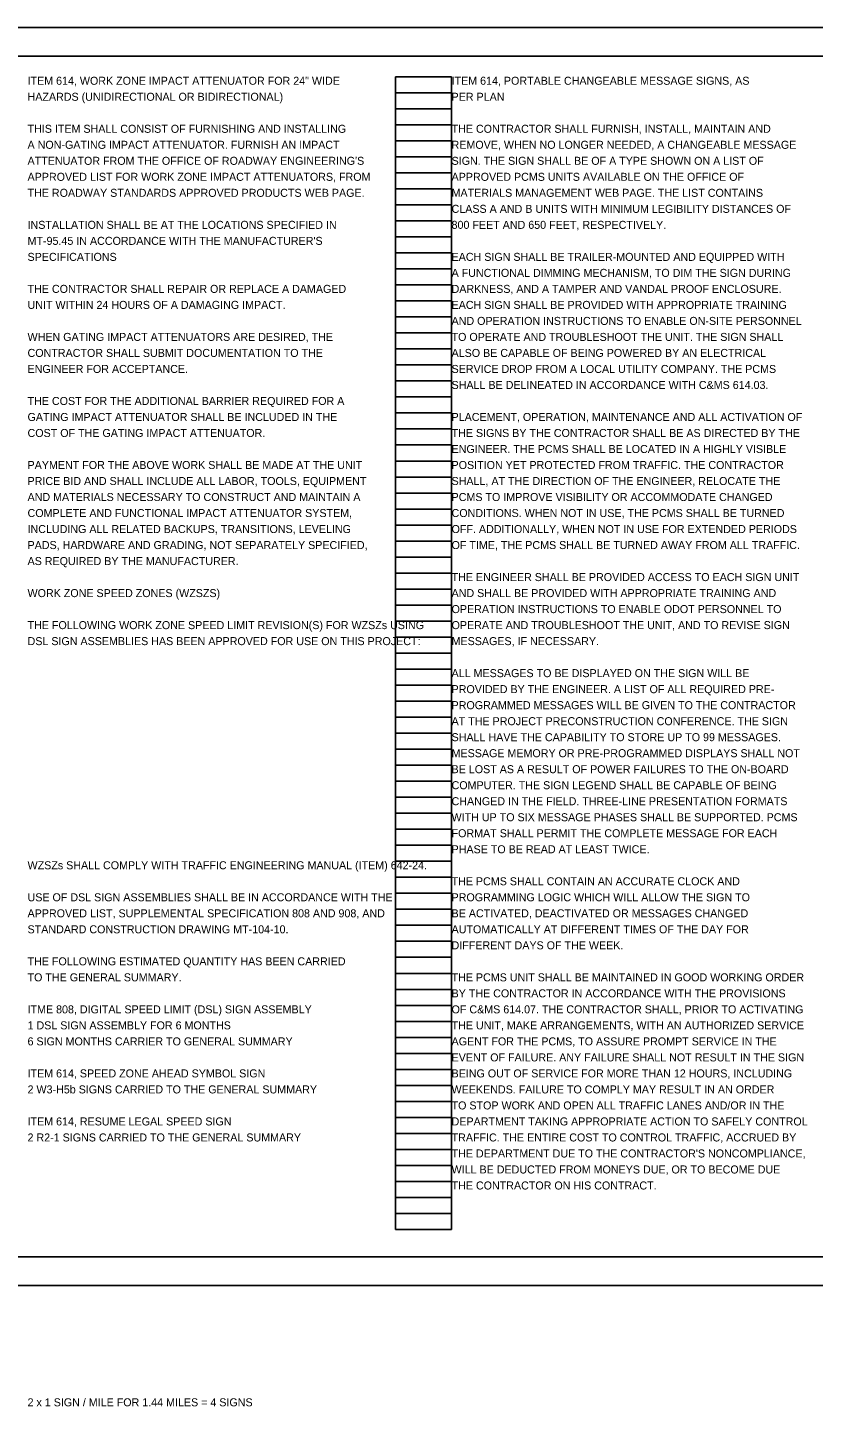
# Model space of a CAD drawing. Extents: x -9 to 65.1, y -15.6 to 23.2.
# Drawn here: x 9.82 to 23.57, y -2.11 to 22 of the extents above; entities that cross this region are included whole.
import ezdxf

# ---------------------------------------------------------------- set-up
doc = ezdxf.new("R2010")
doc.units = 0
for name, color, linetype in [('SH_Border', 7, 'Continuous'), ('SH_Cut_Line', 7, 'Continuous'), ('SH_Data', 7, 'Continuous'), ('SH_Text', 7, 'Continuous')]:
    doc.layers.add(name, color=color, linetype=linetype)

msp = doc.modelspace()

# ---------------------------------------------------------------- linework, layer by layer
at = {"layer": 'SH_Border'}
msp.add_lwpolyline([(1.5, 21.5), (33.5, 21.5), (33.5, 0.5), (1.5, 0.5)], close=True, dxfattribs=at)
at = {"layer": 'SH_Cut_Line'}
msp.add_lwpolyline([(0, 0), (34, 0), (34, 22), (0, 22)], close=True, dxfattribs=at)
at = {"layer": 'SH_Data'}
for p, q in [((16.26, 0.98), (16.26, 21.14)), ((16.26, 21.14), (17.24, 21.14)), ((17.24, 0.98), (17.24, 21.14)), ((16.26, 20.86), (17.24, 20.86)), ((16.26, 20.58), (17.24, 20.58)), ((16.26, 20.3), (17.24, 20.3)), ((16.26, 20.02), (17.24, 20.02)), ((16.26, 19.74), (17.24, 19.74)), ((16.26, 19.46), (17.24, 19.46)), ((16.26, 19.18), (17.24, 19.18)), ((16.26, 18.9), (17.24, 18.9)), ((16.26, 18.62), (17.24, 18.62)), ((16.26, 18.34), (17.24, 18.34)), ((16.26, 18.06), (17.24, 18.06)), ((16.26, 17.78), (17.24, 17.78)), ((16.26, 17.5), (17.24, 17.5)), ((16.26, 17.22), (17.24, 17.22)), ((16.26, 16.94), (17.24, 16.94)), ((16.26, 16.66), (17.24, 16.66)), ((16.26, 16.38), (17.24, 16.38)), ((16.26, 16.1), (17.24, 16.1)), ((16.26, 15.82), (17.24, 15.82)), ((16.26, 15.54), (17.24, 15.54)), ((16.26, 15.26), (17.24, 15.26)), ((16.26, 14.98), (17.24, 14.98)), ((16.26, 14.7), (17.24, 14.7)), ((16.26, 14.42), (17.24, 14.42)), ((16.26, 14.14), (17.24, 14.14)), ((16.26, 13.86), (17.24, 13.86)), ((16.26, 13.58), (17.24, 13.58)), ((16.26, 13.3), (17.24, 13.3)), ((16.26, 13.02), (17.24, 13.02)), ((16.26, 12.74), (17.24, 12.74)), ((16.26, 12.46), (17.24, 12.46)), ((16.26, 12.18), (17.24, 12.18)), ((16.26, 11.9), (17.24, 11.9)), ((16.26, 11.62), (17.24, 11.62)), ((16.26, 11.34), (17.24, 11.34)), ((16.26, 11.06), (17.24, 11.06)), ((16.26, 10.78), (17.24, 10.78)), ((16.26, 10.5), (17.24, 10.5)), ((16.26, 10.22), (17.24, 10.22)), ((16.26, 9.94), (17.24, 9.94)), ((16.26, 9.66), (17.24, 9.66)), ((16.26, 9.38), (17.24, 9.38)), ((16.26, 9.1), (17.24, 9.1)), ((16.26, 8.82), (17.24, 8.82)), ((16.26, 8.54), (17.24, 8.54)), ((16.26, 8.26), (17.24, 8.26)), ((16.26, 7.98), (17.24, 7.98)), ((16.26, 7.7), (17.24, 7.7)), ((16.26, 7.42), (17.24, 7.42)), ((16.26, 7.14), (17.24, 7.14)), ((16.26, 6.86), (17.24, 6.86)), ((16.26, 6.58), (17.24, 6.58)), ((16.26, 6.3), (17.24, 6.3)), ((16.26, 6.02), (17.24, 6.02)), ((16.26, 5.74), (17.24, 5.74)), ((16.26, 5.46), (17.24, 5.46)), ((16.26, 5.18), (17.24, 5.18)), ((16.26, 4.9), (17.24, 4.9)), ((16.26, 4.62), (17.24, 4.62)), ((16.26, 4.34), (17.24, 4.34)), ((16.26, 4.06), (17.24, 4.06)), ((16.26, 3.78), (17.24, 3.78)), ((16.26, 3.5), (17.24, 3.5)), ((16.26, 3.22), (17.24, 3.22)), ((16.26, 2.94), (17.24, 2.94)), ((16.26, 2.66), (17.24, 2.66)), ((16.26, 2.38), (17.24, 2.38)), ((16.26, 2.1), (17.24, 2.1)), ((16.26, 1.82), (17.24, 1.82)), ((16.26, 1.54), (17.24, 1.54)), ((16.26, 1.26), (17.24, 1.26)), ((16.26, 0.98), (17.24, 0.98))]:
    msp.add_line(p, q, dxfattribs=at)

# ---------------------------------------------------------------- texts
at = {"layer": 'SH_Text'}
for s, p in [('ITEM 614, WORK ZONE IMPACT ATTENUATOR FOR 24" WIDE', (9.82, 21)), ('ITEM 614, PORTABLE CHANGEABLE MESSAGE SIGNS, AS', (17.24, 21)), ('HAZARDS (UNIDIRECTIONAL OR BIDIRECTIONAL)', (9.82, 20.72)), ('PER PLAN', (17.24, 20.72)), ('THIS ITEM SHALL CONSIST OF FURNISHING AND INSTALLING', (9.82, 20.16)), ('THE CONTRACTOR SHALL FURNISH, INSTALL, MAINTAIN AND', (17.24, 20.16)), ('A NON-GATING IMPACT ATTENUATOR. FURNISH AN IMPACT', (9.82, 19.88)), ('REMOVE, WHEN NO LONGER NEEDED, A CHANGEABLE MESSAGE', (17.24, 19.88)), ("ATTENUATOR FROM THE OFFICE OF ROADWAY ENGINEERING'S", (9.82, 19.6)), ('SIGN. THE SIGN SHALL BE OF A TYPE SHOWN ON A LIST OF', (17.24, 19.6)), ('APPROVED LIST FOR WORK ZONE IMPACT ATTENUATORS, FROM', (9.82, 19.32)), ('APPROVED PCMS UNITS AVAILABLE ON THE OFFICE OF', (17.24, 19.32)), ('THE ROADWAY STANDARDS APPROVED PRODUCTS WEB PAGE.', (9.82, 19.04)), ('MATERIALS MANAGEMENT WEB PAGE. THE LIST CONTAINS', (17.24, 19.04)), ('CLASS A AND B UNITS WITH MINIMUM LEGIBILITY DISTANCES OF', (17.24, 18.76)), ('INSTALLATION SHALL BE AT THE LOCATIONS SPECIFIED IN', (9.82, 18.48)), ('800 FEET AND 650 FEET, RESPECTIVELY.', (17.24, 18.48)), ("MT-95.45 IN ACCORDANCE WITH THE MANUFACTURER'S", (9.82, 18.2)), ('SPECIFICATIONS', (9.82, 17.92)), ('EACH SIGN SHALL BE TRAILER-MOUNTED AND EQUIPPED WITH', (17.24, 17.92)), ('A FUNCTIONAL DIMMING MECHANISM, TO DIM THE SIGN DURING', (17.24, 17.64)), ('THE CONTRACTOR SHALL REPAIR OR REPLACE A DAMAGED', (9.82, 17.36)), ('DARKNESS, AND A TAMPER AND VANDAL PROOF ENCLOSURE.', (17.24, 17.36)), ('UNIT WITHIN 24 HOURS OF A DAMAGING IMPACT.', (9.82, 17.08)), ('EACH SIGN SHALL BE PROVIDED WITH APPROPRIATE TRAINING', (17.24, 17.08)), ('AND OPERATION INSTRUCTIONS TO ENABLE ON-SITE PERSONNEL', (17.24, 16.8)), ('WHEN GATING IMPACT ATTENUATORS ARE DESIRED, THE', (9.82, 16.52)), ('TO OPERATE AND TROUBLESHOOT THE UNIT. THE SIGN SHALL', (17.24, 16.52)), ('CONTRACTOR SHALL SUBMIT DOCUMENTATION TO THE', (9.82, 16.24)), ('ALSO BE CAPABLE OF BEING POWERED BY AN ELECTRICAL', (17.24, 16.24)), ('ENGINEER FOR ACCEPTANCE.', (9.82, 15.96)), ('SERVICE DROP FROM A LOCAL UTILITY COMPANY. THE PCMS', (17.24, 15.96)), ('SHALL BE DELINEATED IN ACCORDANCE WITH C&MS 614.03.', (17.24, 15.68)), ('THE COST FOR THE ADDITIONAL BARRIER REQUIRED FOR A', (9.82, 15.4)), ('GATING IMPACT ATTENUATOR SHALL BE INCLUDED IN THE', (9.82, 15.12)), ('PLACEMENT, OPERATION, MAINTENANCE AND ALL ACTIVATION OF', (17.24, 15.12)), ('COST OF THE GATING IMPACT ATTENUATOR.', (9.82, 14.84)), ('THE SIGNS BY THE CONTRACTOR SHALL BE AS DIRECTED BY THE', (17.24, 14.84)), ('ENGINEER. THE PCMS SHALL BE LOCATED IN A HIGHLY VISIBLE', (17.24, 14.56)), ('PAYMENT FOR THE ABOVE WORK SHALL BE MADE AT THE UNIT', (9.82, 14.28)), ('POSITION YET PROTECTED FROM TRAFFIC. THE CONTRACTOR', (17.24, 14.28)), ('PRICE BID AND SHALL INCLUDE ALL LABOR, TOOLS, EQUIPMENT', (9.82, 14)), ('SHALL, AT THE DIRECTION OF THE ENGINEER, RELOCATE THE', (17.24, 14)), ('AND MATERIALS NECESSARY TO CONSTRUCT AND MAINTAIN A', (9.82, 13.72)), ('PCMS TO IMPROVE VISIBILITY OR ACCOMMODATE CHANGED', (17.24, 13.72)), ('COMPLETE AND FUNCTIONAL IMPACT ATTENUATOR SYSTEM,', (9.82, 13.44)), ('CONDITIONS. WHEN NOT IN USE, THE PCMS SHALL BE TURNED', (17.24, 13.44)), ('INCLUDING ALL RELATED BACKUPS, TRANSITIONS, LEVELING', (9.82, 13.16)), ('OFF. ADDITIONALLY, WHEN NOT IN USE FOR EXTENDED PERIODS', (17.24, 13.16)), ('PADS, HARDWARE AND GRADING, NOT SEPARATELY SPECIFIED,', (9.82, 12.88)), ('OF TIME, THE PCMS SHALL BE TURNED AWAY FROM ALL TRAFFIC.', (17.24, 12.88)), ('AS REQUIRED BY THE MANUFACTURER.', (9.82, 12.6)), ('THE ENGINEER SHALL BE PROVIDED ACCESS TO EACH SIGN UNIT', (17.24, 12.32)), ('WORK ZONE SPEED ZONES (WZSZS)', (9.82, 12.04)), ('AND SHALL BE PROVIDED WITH APPROPRIATE TRAINING AND', (17.24, 12.04)), ('OPERATION INSTRUCTIONS TO ENABLE ODOT PERSONNEL TO', (17.24, 11.76)), ('THE FOLLOWING WORK ZONE SPEED LIMIT REVISION(S) FOR WZSZs USING', (9.82, 11.48)), ('OPERATE AND TROUBLESHOOT THE UNIT, AND TO REVISE SIGN', (17.24, 11.48)), ('DSL SIGN ASSEMBLIES HAS BEEN APPROVED FOR USE ON THIS PROJECT:', (9.82, 11.2)), ('MESSAGES, IF NECESSARY.', (17.24, 11.2)), ('ALL MESSAGES TO BE DISPLAYED ON THE SIGN WILL BE', (17.24, 10.64)), ('PROVIDED BY THE ENGINEER. A LIST OF ALL REQUIRED PRE-', (17.24, 10.36)), ('PROGRAMMED MESSAGES WILL BE GIVEN TO THE CONTRACTOR', (17.24, 10.08)), ('AT THE PROJECT PRECONSTRUCTION CONFERENCE. THE SIGN', (17.24, 9.8)), ('SHALL HAVE THE CAPABILITY TO STORE UP TO 99 MESSAGES.', (17.24, 9.52)), ('MESSAGE MEMORY OR PRE-PROGRAMMED DISPLAYS SHALL NOT', (17.24, 9.24)), ('BE LOST AS A RESULT OF POWER FAILURES TO THE ON-BOARD', (17.24, 8.96)), ('COMPUTER. THE SIGN LEGEND SHALL BE CAPABLE OF BEING', (17.24, 8.68)), ('CHANGED IN THE FIELD. THREE-LINE PRESENTATION FORMATS', (17.24, 8.4)), ('WITH UP TO SIX MESSAGE PHASES SHALL BE SUPPORTED. PCMS', (17.24, 8.12)), ('FORMAT SHALL PERMIT THE COMPLETE MESSAGE FOR EACH', (17.24, 7.84)), ('PHASE TO BE READ AT LEAST TWICE.', (17.24, 7.56)), ('WZSZs SHALL COMPLY WITH TRAFFIC ENGINEERING MANUAL (ITEM) 642-24.', (9.82, 7.28)), ('THE PCMS SHALL CONTAIN AN ACCURATE CLOCK AND', (17.24, 7)), ('USE OF DSL SIGN ASSEMBLIES SHALL BE IN ACCORDANCE WITH THE', (9.82, 6.72)), ('PROGRAMMING LOGIC WHICH WILL ALLOW THE SIGN TO', (17.24, 6.72)), ('APPROVED LIST, SUPPLEMENTAL SPECIFICATION 808 AND 908, AND', (9.82, 6.44)), ('BE ACTIVATED, DEACTIVATED OR MESSAGES CHANGED', (17.24, 6.44)), ('STANDARD CONSTRUCTION DRAWING MT-104-10.', (9.82, 6.16)), ('AUTOMATICALLY AT DIFFERENT TIMES OF THE DAY FOR', (17.24, 6.16)), ('DIFFERENT DAYS OF THE WEEK.', (17.24, 5.88)), ('THE FOLLOWING ESTIMATED QUANTITY HAS BEEN CARRIED', (9.82, 5.6)), ('TO THE GENERAL SUMMARY.', (9.82, 5.32)), ('THE PCMS UNIT SHALL BE MAINTAINED IN GOOD WORKING ORDER', (17.24, 5.32)), ('BY THE CONTRACTOR IN ACCORDANCE WITH THE PROVISIONS', (17.24, 5.04)), ('ITME 808, DIGITAL SPEED LIMIT (DSL) SIGN ASSEMBLY', (9.82, 4.76)), ('OF C&MS 614.07. THE CONTRACTOR SHALL, PRIOR TO ACTIVATING', (17.24, 4.76)), ('1 DSL SIGN ASSEMBLY FOR 6 MONTHS', (9.82, 4.48)), ('THE UNIT, MAKE ARRANGEMENTS, WITH AN AUTHORIZED SERVICE', (17.24, 4.48)), ('6 SIGN MONTHS CARRIER TO GENERAL SUMMARY', (9.82, 4.2)), ('AGENT FOR THE PCMS, TO ASSURE PROMPT SERVICE IN THE', (17.24, 4.2)), ('EVENT OF FAILURE. ANY FAILURE SHALL NOT RESULT IN THE SIGN', (17.24, 3.92)), ('ITEM 614, SPEED ZONE AHEAD SYMBOL SIGN', (9.82, 3.64)), ('BEING OUT OF SERVICE FOR MORE THAN 12 HOURS, INCLUDING', (17.24, 3.64)), ('2 W3-H5b SIGNS CARRIED TO THE GENERAL SUMMARY', (9.82, 3.36)), ('WEEKENDS. FAILURE TO COMPLY MAY RESULT IN AN ORDER', (17.24, 3.36)), ('TO STOP WORK AND OPEN ALL TRAFFIC LANES AND/OR IN THE', (17.24, 3.08)), ('ITEM 614, RESUME LEGAL SPEED SIGN', (9.82, 2.8)), ('DEPARTMENT TAKING APPROPRIATE ACTION TO SAFELY CONTROL', (17.24, 2.8)), ('2 R2-1 SIGNS CARRIED TO THE GENERAL SUMMARY', (9.82, 2.52)), ('TRAFFIC. THE ENTIRE COST TO CONTROL TRAFFIC, ACCRUED BY', (17.24, 2.52)), ("THE DEPARTMENT DUE TO THE CONTRACTOR'S NONCOMPLIANCE,", (17.24, 2.24)), ('WILL BE DEDUCTED FROM MONEYS DUE, OR TO BECOME DUE', (17.24, 1.96)), ('THE CONTRACTOR ON HIS CONTRACT.', (17.24, 1.68)), ('2 x 1 SIGN / MILE FOR 1.44 MILES = 4 SIGNS', (9.82, -2.112))]:
    msp.add_text(s, height=0.14, dxfattribs=at).set_placement(p)

doc.saveas('drawing.dxf')
